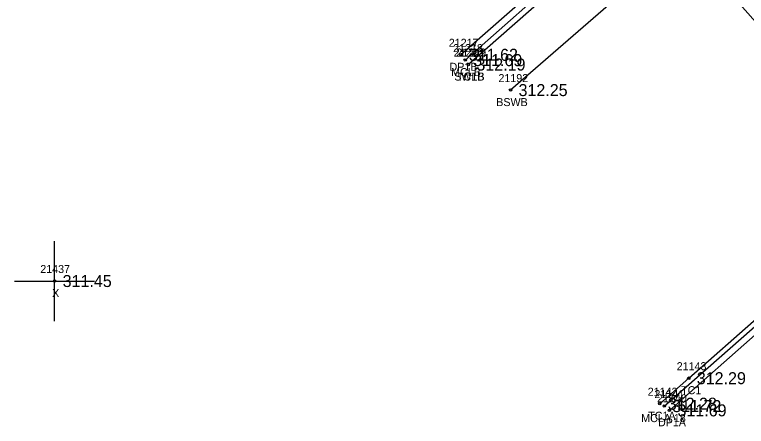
# Model space of a CAD drawing. Extents: x 1970242 to 1971082, y 803104 to 803947.
# Drawn here: x 1970279.7 to 1970371.2, y 803683.2 to 803734.7 of the extents above; entities that cross this region are included whole.
import ezdxf

# ---------------------------------------------------------------- set-up
doc = ezdxf.new("R2010")
doc.units = 0
for name, color, linetype in [('RD_DTM_BkLn2', 7, 'Continuous'), ('RD_EX_Conc', 7, 'Continuous'), ('RD_EX_Conc_txCode', 7, 'Continuous'), ('RD_EX_Driveway', 7, 'Continuous'), ('RD_EX_Driveway_txCode', 7, 'Continuous'), ('RD_EX_Misc', 7, 'Continuous'), ('RD_EX_Misc_txCode', 7, 'Continuous'), ('RD_EX_TX_Conc_ELEV', 7, 'Continuous'), ('RD_EX_TX_Driveway_ELEV', 7, 'Continuous'), ('RD_EX_TX_Misc_ELEV', 7, 'Continuous'), ('RD_SMD_Locator', 7, 'Continuous')]:
    doc.layers.add(name, color=color, linetype=linetype)

msp = doc.modelspace()

# ---------------------------------------------------------------- linework, layer by layer
at = {"layer": 'RD_DTM_BkLn2'}
msp.add_lwpolyline([(1970360.379, 803686.078), (1970364.002, 803689.27), (1970372.797, 803697.031), (1970384.031, 803706.942), (1970388.043, 803714.574), (1970387.812, 803720.9), (1970384.41, 803726.133), (1970362.198, 803751.392), (1970355.314, 803759.382), (1970349.43, 803761.874), (1970344.957, 803761.259), (1970340.617, 803758.255), (1970339.742, 803754.187), (1970341.052, 803750.645), (1970350.072, 803740.463), (1970336.455, 803728.473)], dxfattribs=at)
at = {"layer": 'RD_EX_Conc'}
for points in [[(1970360.928, 803685.78), (1970384.619, 803706.625), (1970388.613, 803714.286), (1970388.403, 803721.009), (1970384.878, 803726.626), (1970355.578, 803759.79), (1970349.519, 803762.244), (1970344.685, 803761.785), (1970340.214, 803758.559), (1970339.209, 803753.867), (1970340.497, 803750.4), (1970349.163, 803740.623), (1970336.054, 803729.022)], [(1970388.043, 803714.574), (1970387.812, 803720.9), (1970384.41, 803726.133), (1970362.198, 803751.392), (1970350.072, 803740.463), (1970336.455, 803728.473)], [(1970388.043, 803714.574), (1970384.866, 803718.144), (1970385.631, 803718.829), (1970368.137, 803738.615), (1970367.294, 803737.93), (1970364.409, 803741.02), (1970364.338, 803740.936), (1970361.218, 803738.424), (1970359.252, 803740.53), (1970341.72, 803725.277)]]:
    msp.add_lwpolyline(points, dxfattribs=at)
at = {"layer": 'RD_EX_Driveway'}
msp.add_lwpolyline([(1970361.584, 803685.25), (1970385.155, 803706.07), (1970389.475, 803713.845), (1970389.303, 803721.405), (1970385.523, 803727.117), (1970356.232, 803760.398), (1970349.717, 803763.304), (1970344.215, 803762.632), (1970339.473, 803759.052), (1970338.114, 803753.777), (1970339.901, 803749.792), (1970347.988, 803740.685), (1970335.512, 803729.688)], dxfattribs=at)
at = {"layer": 'RD_EX_Misc'}
for p, q in [((1970284.739, 803696.415), (1970284.739, 803706.415)), ((1970279.739, 803701.415), (1970289.739, 803701.415))]:
    msp.add_line(p, q, dxfattribs=at)
at = {"layer": 'RD_SMD_Locator'}
for centre in [(1970335.512, 803729.688), (1970336.054, 803729.022), (1970336.455, 803728.473), (1970336.455, 803728.473), (1970341.72, 803725.277), (1970284.739, 803701.415), (1970364.002, 803689.27), (1970360.379, 803686.078), (1970360.928, 803685.78), (1970361.584, 803685.25)]:
    msp.add_circle(centre, 0.15, dxfattribs=at)

# ---------------------------------------------------------------- texts
at = {"layer": 'RD_EX_Conc_txCode'}
for s, p in [('21218', (1970334.542, 803730.022)), ('21220', (1970334.621, 803729.473)), ('21219', (1970334.944, 803729.473)), ('MCLB', (1970334.29, 803727.022)), ('SWLB', (1970334.692, 803726.473)), ('TC1B', (1970335.022, 803726.473)), ('21192', (1970340.208, 803726.277)), ('BSWB', (1970339.933, 803723.277)), ('21143', (1970362.49, 803690.27)), ('21142', (1970358.867, 803687.078)), ('TC1', (1970363.041, 803687.27)), ('21141', (1970359.7, 803686.78)), ('MCLA 18', (1970358.046, 803683.78)), ('TC1A', (1970358.93, 803684.078))]:
    msp.add_text(s, height=1, dxfattribs=at).set_placement(p)
at = {"layer": 'RD_EX_Driveway_txCode'}
for s, p in [('21217', (1970334, 803730.688)), ('DP1B', (1970334.095, 803727.688)), ('21140', (1970360.033, 803686.25)), ('DP1A', (1970360.151, 803683.25))]:
    msp.add_text(s, height=1, dxfattribs=at).set_placement(p)
at = {"layer": 'RD_EX_Misc_txCode'}
for s, p in [('21437', (1970282.943, 803702.415)), ('X', (1970284.424, 803699.415))]:
    msp.add_text(s, height=1, dxfattribs=at).set_placement(p)
at = {"layer": 'RD_EX_TX_Conc_ELEV'}
for s, p in [('311.69', (1970337.054, 803728.272)), ('312.19', (1970337.455, 803727.723)), ('312.19', (1970337.455, 803727.723)), ('312.25', (1970342.72, 803724.527)), ('312.29', (1970365.002, 803688.52)), ('312.28', (1970361.379, 803685.328)), ('311.72', (1970361.928, 803685.03))]:
    msp.add_text(s, height=1.5, dxfattribs=at).set_placement(p)
at = {"layer": 'RD_EX_TX_Driveway_ELEV'}
for s, p in [('311.62', (1970336.512, 803728.938)), ('311.69', (1970362.584, 803684.5))]:
    msp.add_text(s, height=1.5, dxfattribs=at).set_placement(p)
at = {"layer": 'RD_EX_TX_Misc_ELEV'}
msp.add_text('311.45', height=1.5, dxfattribs=at).set_placement((1970285.739, 803700.665))

doc.saveas('drawing.dxf')
